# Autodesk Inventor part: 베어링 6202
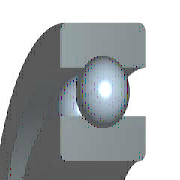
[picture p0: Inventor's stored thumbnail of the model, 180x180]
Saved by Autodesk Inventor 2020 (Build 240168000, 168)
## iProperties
Company: 한국ATC센터
IsCustomPart: 1
Created: 2015-12
Part Number: 베어링 6202
Material: 강철, 연강
Description: 깊은 그루브 볼 베어링
Document SubType Name: Modeling
Standard: KS B 2023
Designer: mdu
Standards Organization: KS
Language: ko-KR
Size Designation: 6202 - 15 x 35 x 11
Categories: <MemberInstance><Categories><Category DisplayName="샤프트 부품" InternalName="7f7aeb1f-a693-4053-b835-cee3144e0d98" Mnemonic="SHFT"><Category DisplayName="베어링" Inter
Density: 7.86 g/cm^3
Mass: 45.8724 g
Surface Area: 51.5584 cm^2
Volume: 5.83618 cm^3
Appearance: 주황색
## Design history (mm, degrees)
sketch "스케치" dims "d0" = 5.2 (= -0.26 x WD + 0.26 x BD)
  geometry: L1 (2.9, 12.5)-(8.1, 12.5); L2 (5.5, 12.5)-(5.5, 9.9); L3 (5.5, 12.5)-(5.5, 15.1); L4 (3.568, 10.76)-(0, 10.76); L5 (0, 7.5)-(11, 7.5); L6 (3.568, 14.24)-(0, 14.24); L7 (0, 17.5)-(11, 17.5); L8 (11, 7.5)-(11, 10.76); L9 (7.432, 10.76)-(11, 10.76); L10 (7.432, 14.24)-(11, 14.24); L11 (11, 17.5)-(11, 14.24); L12 (-1.4, 0)-(8.4, 0) reference; L13 (0, -0.3)-(0, 5.3) reference
  constraints: 22 end point, 4 point on line, 2 collinear, 2 perpendicular, 2 symmetric about line, 1 midpoint, 1 parallel, 14 other
  dimensions: "d9" = 15 diameter of L5 L12 (= WD); "d11" = 35 diameter of L7 L12 (= BD); "d12" = 11 distance between parallel lines of L8 L13 (= KB); "d13" = 21.52 diameter of L9 L12 (= 0.326 x BD + 0.674 x WD)
revolve "본체" stored, may be unused: angle "d6" = 90 deg
revolve "볼" stored, may be unused: angle "d7" = 90 deg
pattern_circular "IDS_ARRAYBALL[SIMPL:T]" dims angle "d3" = 360 deg
body "Solid1"
fillet "모깎기1" dims "d1" = 0.6 (= KRS)
other parameters: "WD" = 15 [user parameter; used in 5 equation terms], "BD" = 35 [user parameter; used in 5 equation terms], "KB" = 11 [user parameter; used in 1 equation term], "KRS" = 0.6 [user parameter; used in 1 equation term], "d4" = 0, "d5" = 0, "d8" = 0, "d14" = 0, "d15" = 0, "BBA" = 0 [user parameter], "BC0" = 3750000 [user parameter], "BC" = 7800000 [user parameter], "BR" = 17.5 (= 0.5 x BD) [user parameter], "WR" = 7.5 (= 0.5 x WD) [user parameter]
